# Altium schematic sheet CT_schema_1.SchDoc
size 527 x 258 mm
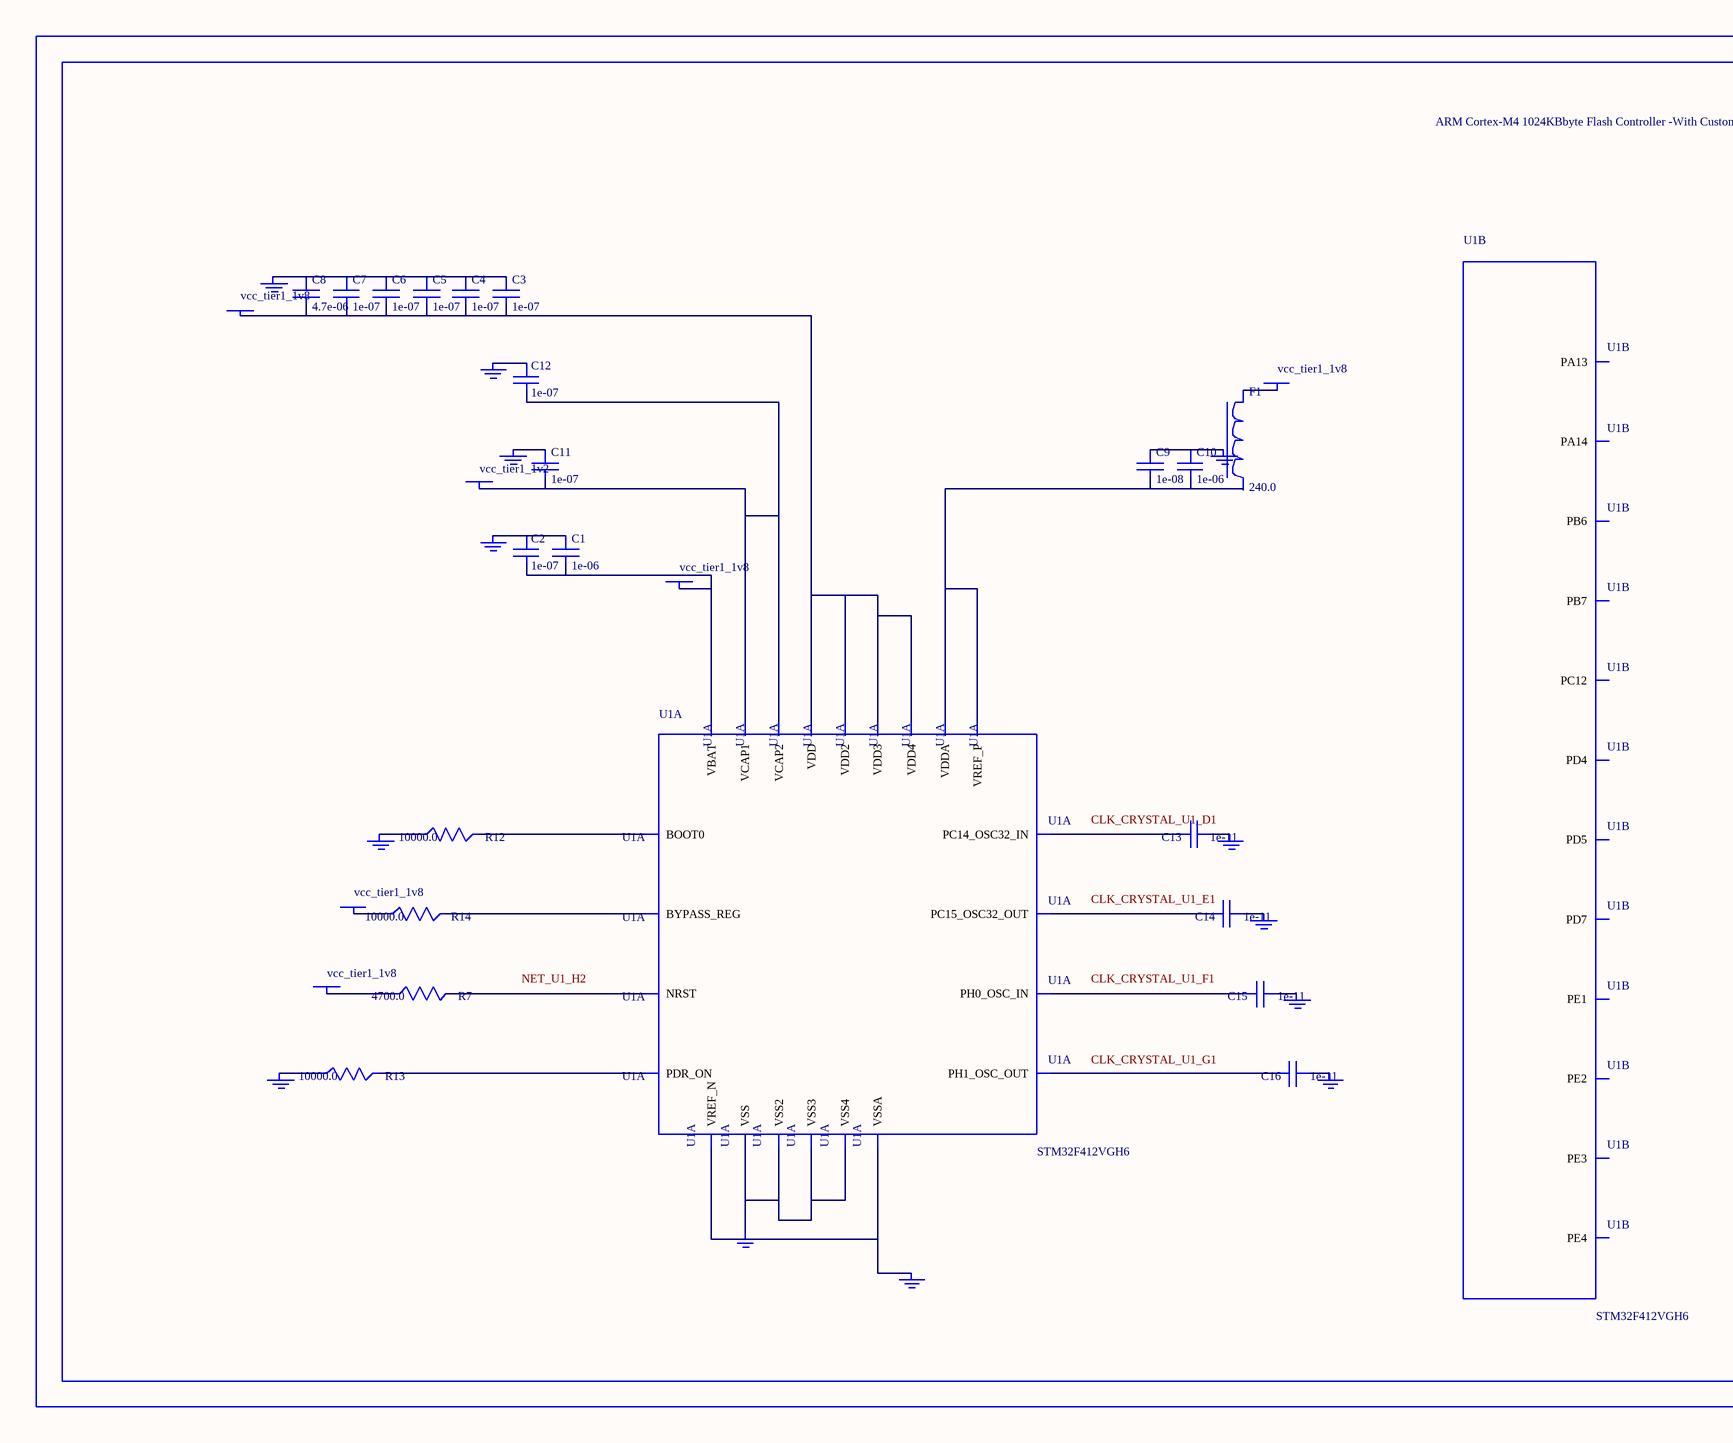
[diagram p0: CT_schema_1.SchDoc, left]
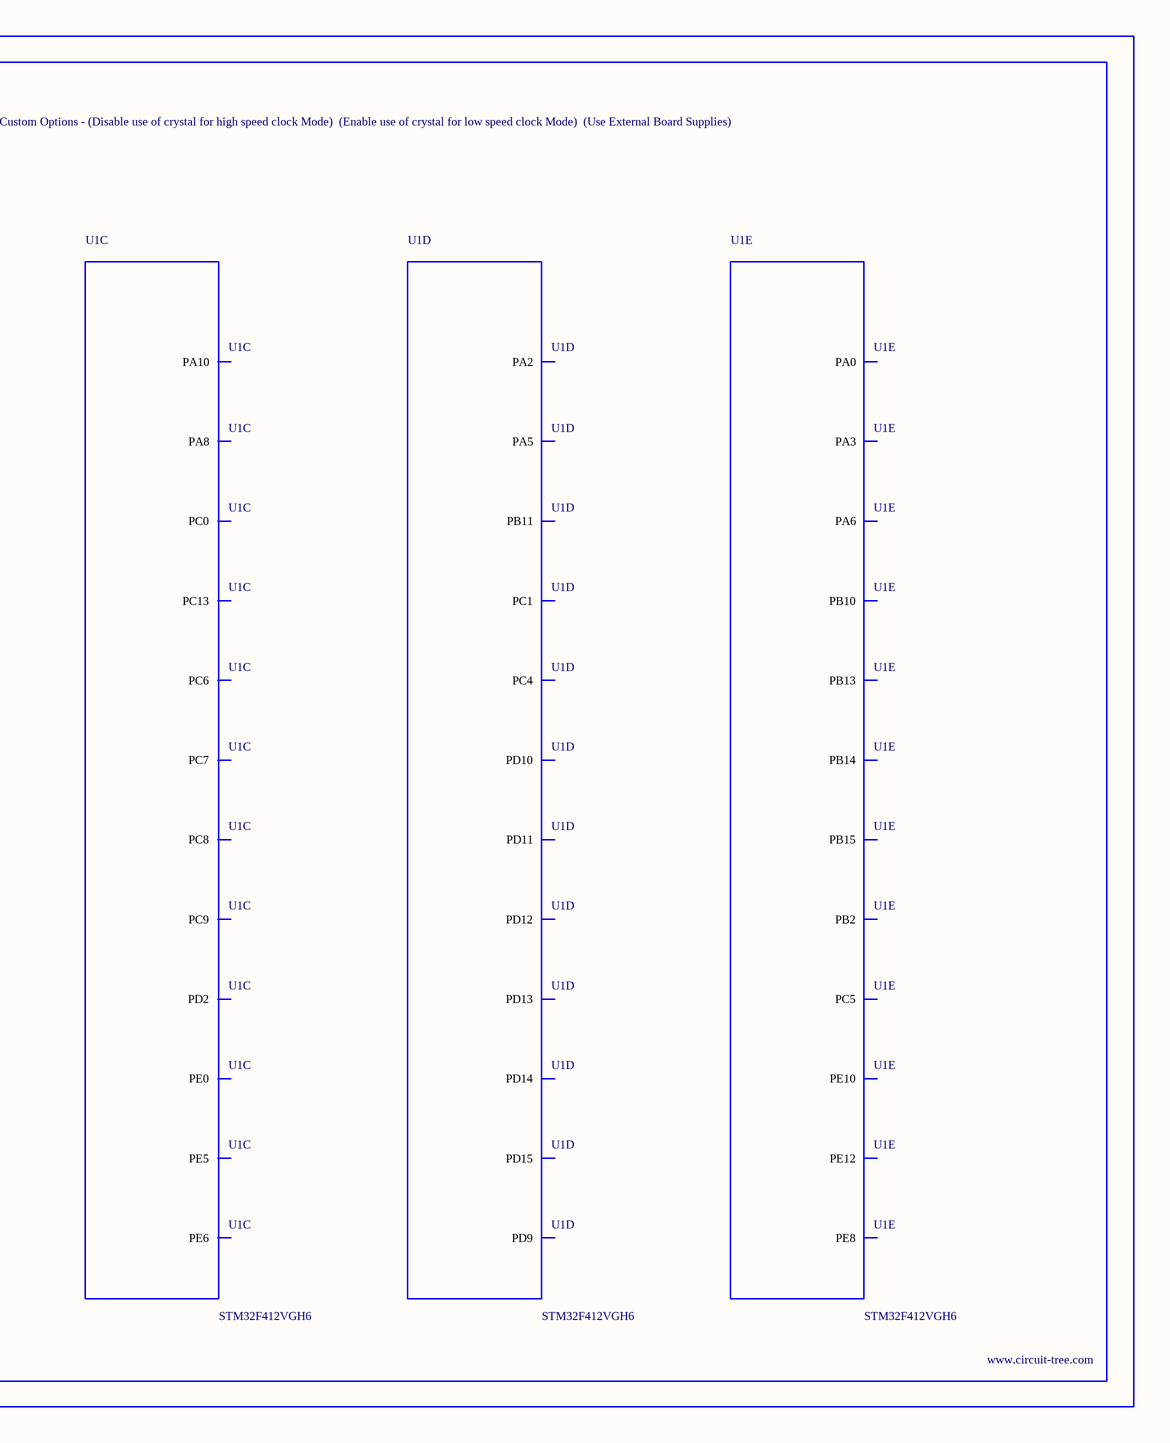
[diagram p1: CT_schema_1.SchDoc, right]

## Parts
BORDER0  (no value)
C1  1e-06  [C0603]
C2  1e-07  [C0603]
C3  1e-07  [C0603]
C4  1e-07  [C0603]
C5  1e-07  [C0603]
C6  1e-07  [C0603]
C7  1e-07  [C0603]
C8  4.7e-06  [C0603]
C9  1e-08  [C0603]
C10  1e-06  [C0603]
C11  1e-07  [C0402]
C12  1e-07  [C0402]
C13  1e-11  [C0402]
C14  1e-11  [C0402]
C15  1e-11  [C0402]
C16  1e-11  [C0402]
F1  240.0  [L0603]
GND_INSTANCE_0_0  (no value)
GND_INSTANCE_0_1  (no value)
GND_INSTANCE_0_2  (no value)
GND_INSTANCE_0_3  (no value)
GND_INSTANCE_0_4  (no value)
GND_INSTANCE_0_5  (no value)
GND_INSTANCE_0_6  (no value)
GND_INSTANCE_0_7  (no value)
GND_INSTANCE_0_8  (no value)
GND_INSTANCE_0_9  (no value)
GND_INSTANCE_0_10  (no value)
GND_INSTANCE_0_11  (no value)
GND_INSTANCE_0_12  (no value)
POWER_INSTANCE_0_0  vcc_tier1_1v8
POWER_INSTANCE_0_1  vcc_tier1_1v8
POWER_INSTANCE_0_2  vcc_tier1_1v8
POWER_INSTANCE_0_3  vcc_tier1_1v8
POWER_INSTANCE_0_4  vcc_tier1_1v2
POWER_INSTANCE_0_5  vcc_tier1_1v8
R7  4700.0  [R0603]
R12  10000.0  [R0603]
R13  10000.0  [R0603]
R14  10000.0  [R0603]
U1  STM32F412VGH6  [UFBGA100]  (parts A,B,C,D,E of 11)

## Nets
NetC1_1: C1.1 C2.1 GND_INSTANCE_0_0.0(GND)
NetC1_2: C1.2 C2.2 POWER_INSTANCE_0_0.0(PWR) U1.E2(VBAT)
NetC3_1: C3.1 C4.1 C5.1 C6.1 C7.1 C8.1 GND_INSTANCE_0_2.0(GND)
NetC3_2: C3.2 C4.2 C5.2 C6.2 C7.2 C8.2 POWER_INSTANCE_0_2.0(PWR) U1.C4(VDD) U1.G2(VDD4) U1.G11(VDD2) U1.G12(VDD3)
NetC9_1: C9.1 C10.1 GND_INSTANCE_0_1.0(GND)
NetC9_2: C9.2 C10.2 U1.L1(VREF_P) U1.M1(VDDA)
NetC11_1: C11.1 GND_INSTANCE_0_5.0(GND)
NetC11_2: C11.2 C12.2 POWER_INSTANCE_0_4.0(PWR) U1.C11(VCAP2) U1.L11(VCAP1)
NetC12_1: C12.1 GND_INSTANCE_0_6.0(GND)
NetC13_1: C13.1 GND_INSTANCE_0_7.0(GND)
NetC13_2: C13.2 U1.D1(PC14_OSC32_IN)
NetC14_1: C14.1 GND_INSTANCE_0_8.0(GND)
NetC14_2: C14.2 U1.E1(PC15_OSC32_OUT)
NetC15_1: C15.1 GND_INSTANCE_0_9.0(GND)
NetC15_2: C15.2 U1.F1(PH0_OSC_IN)
NetC16_1: C16.1 GND_INSTANCE_0_10.0(GND)
NetC16_2: C16.2 U1.G1(PH1_OSC_OUT)
NetF1_1: F1.1 POWER_INSTANCE_0_1.0(PWR)
NetGND_INSTANCE_0_3_0: GND_INSTANCE_0_3.0(GND) R12.1
NetGND_INSTANCE_0_4_0: GND_INSTANCE_0_4.0(GND) R13.1
NetGND_INSTANCE_0_11_0: GND_INSTANCE_0_11.0(GND) U1.J1(VSSA) U1.K1(VREF_N)
NetGND_INSTANCE_0_12_0: GND_INSTANCE_0_12.0(GND) U1.D3(VSS) U1.F2(VSS4) U1.F11(VSS2) U1.F12(VSS3)
NetPOWER_INSTANCE_0_3_0: POWER_INSTANCE_0_3.0(PWR) R14.1
NetPOWER_INSTANCE_0_5_0: POWER_INSTANCE_0_5.0(PWR) R7.1
NetR7_2: R7.2 U1.H2(NRST)
NetR12_2: R12.2 U1.A4(BOOT0)
NetR13_2: R13.2 U1.H3(PDR_ON)
NetR14_2: R14.2 U1.E3(BYPASS_REG)

Not connected (* = marked no-connect by the designer): F1 2; U1 A1(PE3) A2(PE1) A5(PD7) A6(PD5) A10(PA14) A11(PA13) B1(PE4) B2(PE2) B4(PB7) B5(PB6) B7(PD4) B10(PC12) C1(PC13) C2(PE5) C3(PE0) C8(PD2) C12(PA10) D2(PE6) D11(PA8) D12(PC9) E10(PC8) E11(PC7) E12(PC6) H1(PC0) H10(PD15) H11(PD14) H12(PD13) J2(PC1) J10(PD12) J11(PD11) J12(PD10) K3(PA2) K4(PA5) K5(PC4) K8(PD9) K9(PB11) K10(PB15) K11(PB14) K12(PB13) L2(PA0) L3(PA3) L4(PA6) L5(PC5) L6(PB2) L7(PE8) L8(PE10) L9(PE12) L10(PB10)

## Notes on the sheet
- Labels drawn without touching a wire or pin: CLK_CRYSTAL_U1_D1, CLK_CRYSTAL_U1_E1, CLK_CRYSTAL_U1_F1, CLK_CRYSTAL_U1_G1, NET_U1_H2

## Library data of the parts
BORDER0 = BORDER_PAGE0
C1 C10 = C0603C105K3RACTU
C2-C7 = 06035C104K4Z2A
C8 = GRM188R6YA475KE15D
C9 = 06035C103K4Z2A
C11 C12 = C0402C104K3RACTU
C13-C16 = C0402C100K3GACTU
F1 = Z0603C241ASMST
GND_INSTANCE_0_0-GND_INSTANCE_0_12 = GND
POWER_INSTANCE_0_0-POWER_INSTANCE_0_5 = PWR
R7 = RC0603JR-074K7L
R12-R14 = RC0603JR-0710KL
